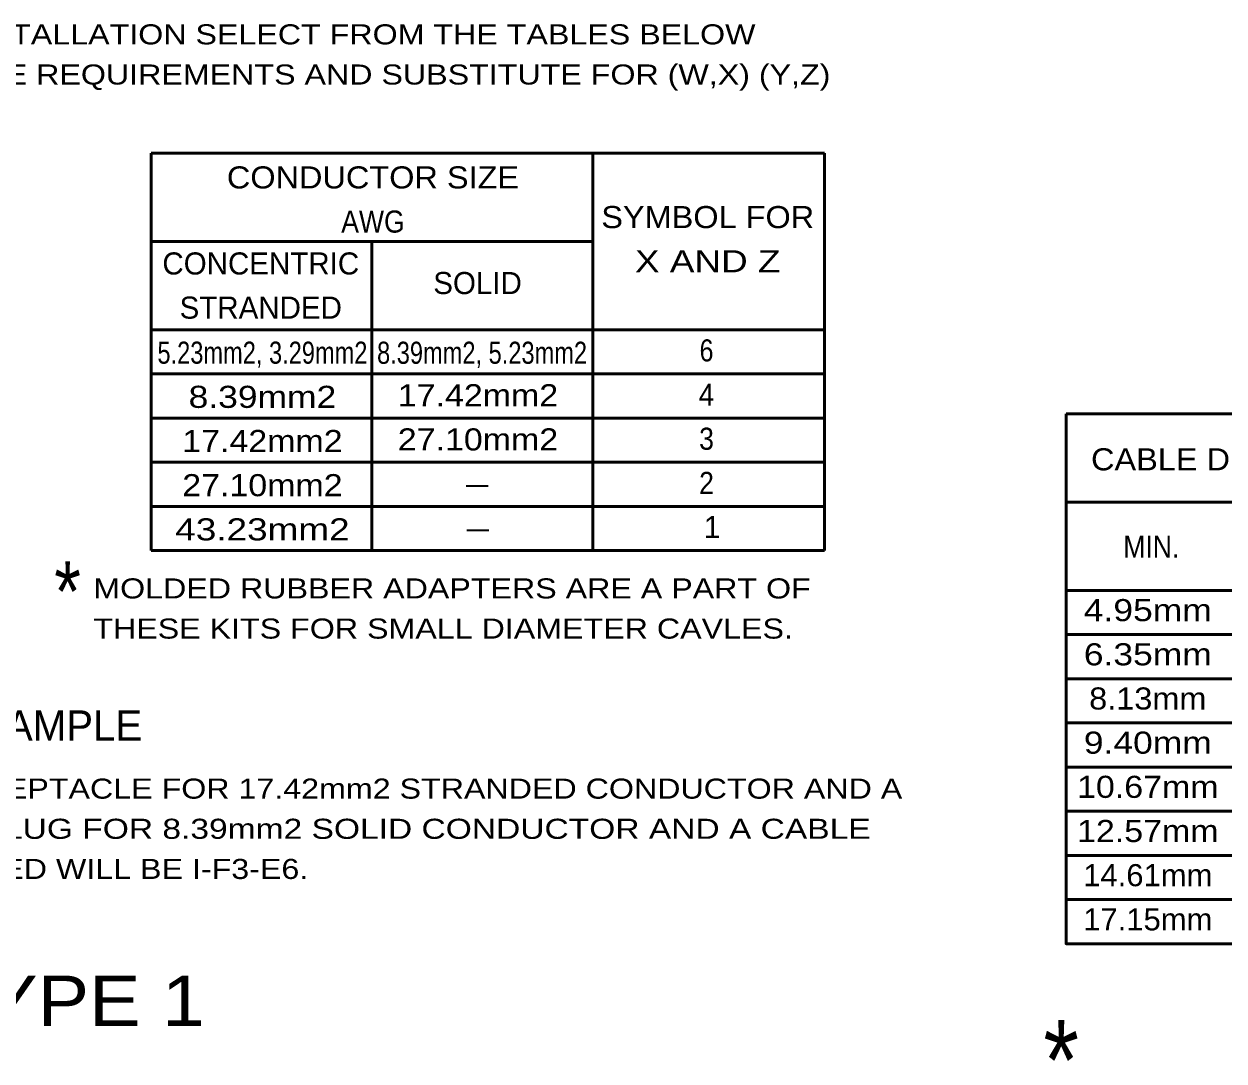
# Model space of a CAD drawing. Extents: x -32 to 824, y -6 to 538.
# Drawn here: x 154.8 to 298.3, y 274.4 to 398.4 of the extents above; entities that cross this region are included whole.
import ezdxf
from ezdxf.enums import TextEntityAlignment as Align

# ---------------------------------------------------------------- set-up
doc = ezdxf.new("R2010")
doc.units = 0
doc.header["$LTSCALE"] = 1.1
doc.layers.add('1', color=7, linetype='Continuous', lineweight=53)

msp = doc.modelspace()

# ---------------------------------------------------------------- linework, layer by layer
at = {"layer": '1'}
for p, q in [((250.529, 382.928), (170.009, 382.928)), ((170.009, 382.928), (170.009, 335.408)), ((222.809, 382.928), (222.809, 335.408)), ((250.529, 382.928), (250.529, 335.408)), ((222.809, 372.368), (170.009, 372.368)), ((196.409, 372.368), (196.409, 335.408)), ((250.529, 361.808), (170.009, 361.808)), ((250.529, 356.528), (170.009, 356.528)), ((250.529, 351.248), (170.009, 351.248)), ((250.529, 345.968), (170.009, 345.968)), ((250.529, 340.688), (170.009, 340.688)), ((279.435, 341.218), (319.035, 341.218)), ((250.529, 335.408), (170.009, 335.408)), ((279.435, 330.658), (338.835, 330.658)), ((279.435, 325.378), (338.835, 325.378)), ((279.435, 320.098), (338.835, 320.098)), ((279.435, 314.818), (338.835, 314.818)), ((279.435, 309.538), (338.835, 309.538)), ((279.435, 304.258), (338.835, 304.258)), ((279.435, 298.978), (338.835, 298.978)), ((279.435, 293.698), (338.835, 293.698))]:
    msp.add_line(p, q, dxfattribs=at)
at = {"layer": '1', "lineweight": 35}
for p, q in [((207.679, 343.165), (210.319, 343.165)), ((207.752, 337.839), (210.392, 337.839))]:
    msp.add_line(p, q, dxfattribs=at)
at = {"layer": '1'}
msp.add_lwpolyline([(279.435, 351.778), (338.835, 351.778), (338.835, 288.418), (279.435, 288.418)], close=True, dxfattribs=at)

# ---------------------------------------------------------------- texts
for s, height, width, p in [('TO SPECIFY THE PROPER KIT FOR AN INSTALLATION SELECT FROM THE TABLES BELOW', 2.4, 1.2, (74.084, 395.916)), ('THE SYMBOLS WHICH COINCIDE WITH THE REQUIREMENTS AND SUBSTITUTE FOR (W,X) (Y,Z)', 2.4, 1.2, (74.084, 391.116)), ('CABLE DIAMETER', 2.64, 1.1, (282.414, 345.002)), ('MIN.', 2.64, 0.9, (286.266, 334.557)), ('*', 7.2, 0.85, (158.413, 326.927)), ('MOLDED RUBBER ADAPTERS ARE A PART OF', 2.4, 1.2, (163.08, 329.691)), ('THESE KITS FOR SMALL DIAMETER CAVLES.', 2.4, 1.2, (163.08, 324.891)), ('IF THE INSTALLATION REQUIRES A RECEPTACLE FOR 17.42mm2 STRANDED CONDUCTOR AND A', 2.4, 1.2, (77.943, 305.761)), ('CABLE DIAMETER OF 16.7mm AND A PLUG FOR 8.39mm2 SOLID CONDUCTOR AND A CABLE', 2.4, 1.25, (77.943, 300.961)), ('DIAMETER OF 11.7mm, THE KIT REQUIRED WILL BE I-F3-E6.', 2.4, 1.2, (77.943, 296.161)), ('*', 9.6, 0.85, (276.718, 269.706))]:
    msp.add_text(s, height=height, dxfattribs=dict(at, width=width)).set_placement(p)
for s, height, width, p in [('CONDUCTOR SIZE', 2.64, 1.1, (196.531, 378.699)), ('AWG', 2.64, 0.9, (196.531, 373.419)), ('SYMBOL FOR', 2.64, 1.1, (236.568, 373.957)), ('X AND Z', 2.64, 1.25, (236.568, 368.677)), ('5.23mm2, 3.29mm2', 2.64, 0.8, (183.308, 357.75)), ('8.39mm2, 5.23mm2', 2.64, 0.8, (209.577, 357.739)), ('6', 2.64, 0.85, (236.423, 358.022)), ('8.39mm2', 2.64, 1.2, (183.308, 352.47)), ('17.42mm2', 2.64, 1.15, (209.089, 352.662)), ('4', 2.64, 0.95, (236.423, 352.742)), ('17.42mm2', 2.64, 1.15, (183.308, 347.19)), ('27.10mm2', 2.64, 1.15, (209.089, 347.382)), ('3', 2.64, 0.9, (236.423, 347.462)), ('27.10mm2', 2.64, 1.15, (183.308, 341.91)), ('2', 2.64, 0.9, (236.423, 342.182)), ('43.23mm2', 2.64, 1.25, (183.308, 336.63)), ('4.95mm', 2.64, 1.2, (289.201, 326.976)), ('6.35mm', 2.64, 1.2, (289.201, 321.696)), ('8.13mm', 2.64, 1.1, (289.201, 316.416)), ('9.40mm', 2.64, 1.2, (289.201, 311.136)), ('10.67mm', 2.64, 1.15, (289.201, 305.856)), ('12.57mm', 2.64, 1.15, (289.201, 300.576)), ('14.61mm', 2.64, 1.05, (289.201, 295.296)), ('17.15mm', 2.64, 1.05, (289.201, 290.016)), ('TYPE 1', 6, 1.15, (160.53, 278.606))]:
    msp.add_text(s, height=height, dxfattribs=dict(at, width=width)).set_placement(p, align=Align.CENTER)
for s, p in [('CONCENTRIC', (183.112, 368.413)), ('STRANDED', (183.112, 363.133)), ('1', (237.091, 336.902))]:
    msp.add_text(s, height=2.64, dxfattribs=at).set_placement(p, align=Align.CENTER)
for s, height, p in [('SOLID', 2.64, (203.741, 366.072)), ('EXAMPLE', 3.6, (146.197, 312.711))]:
    msp.add_text(s, height=height, dxfattribs=at).set_placement(p)

doc.saveas('drawing.dxf')
